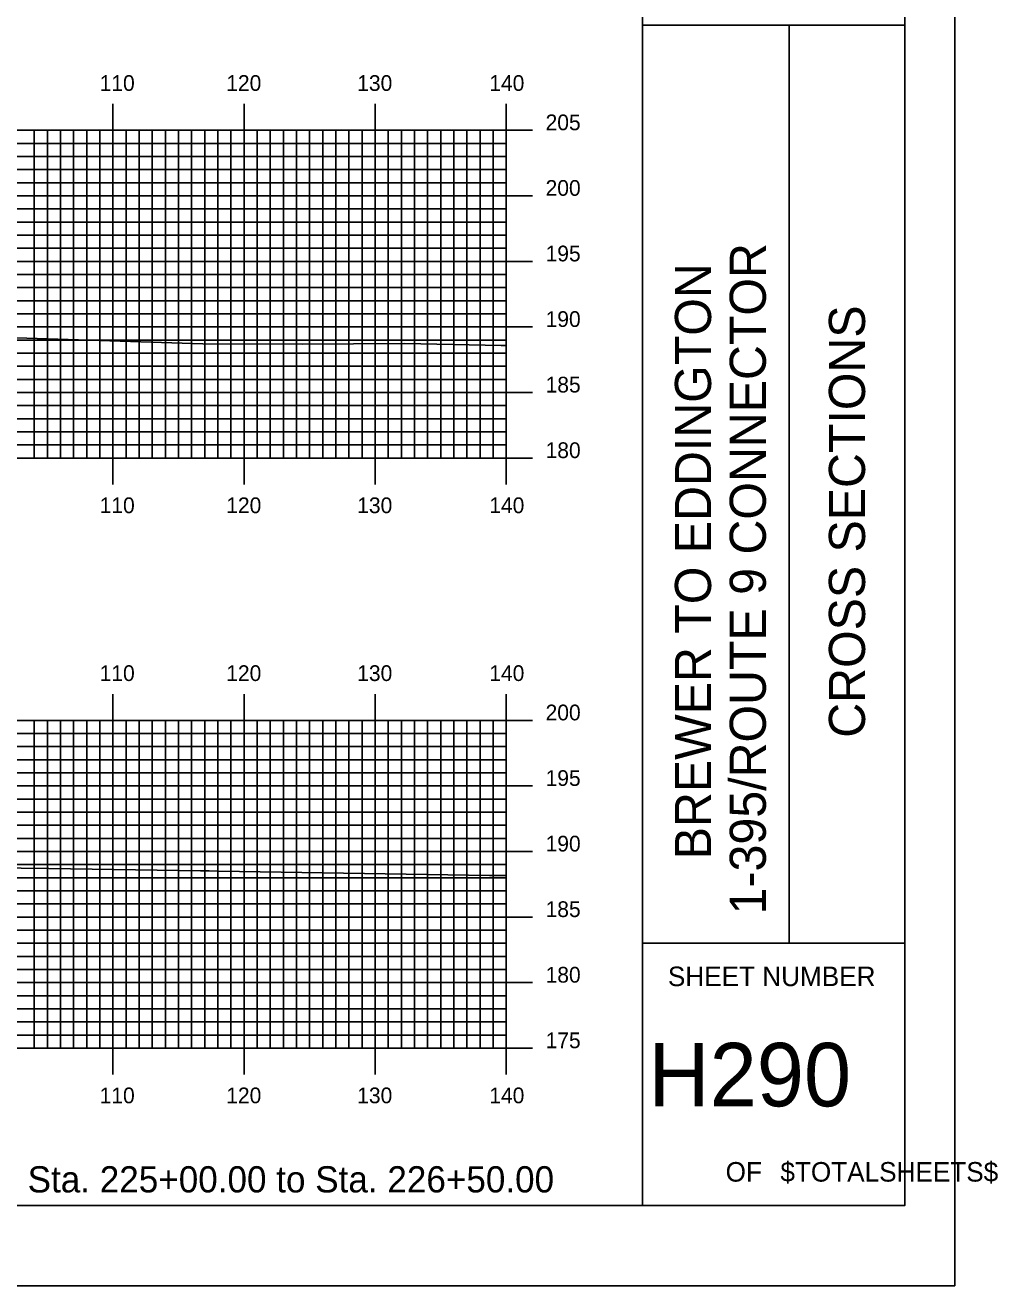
# Model space of a CAD drawing. Extents: x 1798388 to 1798731, y 442591 to 442811.
# Drawn here: x 1798656.8 to 1798731, y 442590.5 to 442686.7 of the extents above; entities that cross this region are included whole.
import ezdxf

# ---------------------------------------------------------------- set-up
doc = ezdxf.new("R2010")
doc.units = 0
for name, color, linetype in [('BORDER', 7, 'Continuous'), ('H_V ANNOTATION', 7, 'Continuous'), ('MAJOR', 7, 'Continuous'), ('MINOR', 7, 'Continuous'), ('PLOT BOUNDARY', 7, 'Continuous'), ('S_Roadway_Centerline', 7, 'Continuous')]:
    doc.layers.add(name, color=color, linetype=linetype)

msp = doc.modelspace()

# ---------------------------------------------------------------- linework, layer by layer
at = {"layer": 'BORDER'}
for p, q in [((1798703.871, 442596.665), (1798703.871, 442806.665)), ((1798703.871, 442686.671), (1798723.871, 442686.671)), ((1798715.053, 442616.671), (1798715.053, 442686.671)), ((1798703.871, 442616.671), (1798723.871, 442616.671))]:
    msp.add_line(p, q, dxfattribs=at)
msp.add_lwpolyline([(1798403.871, 442596.665), (1798723.871, 442596.665), (1798723.871, 442806.665), (1798403.871, 442806.665)], close=True, dxfattribs=at)
at = {"layer": 'MAJOR'}
for p, q in [((1798663.471, 442680.669), (1798663.471, 442678.665)), ((1798673.471, 442680.669), (1798673.471, 442678.665)), ((1798683.471, 442680.669), (1798683.471, 442678.665)), ((1798693.471, 442680.669), (1798693.471, 442678.665)), ((1798413.471, 442678.665), (1798693.471, 442678.665)), ((1798413.471, 442678.665), (1798693.471, 442678.665)), ((1798663.471, 442653.665), (1798663.471, 442678.665)), ((1798673.471, 442653.665), (1798673.471, 442678.665)), ((1798683.471, 442653.665), (1798683.471, 442678.665)), ((1798695.475, 442678.665), (1798691.467, 442678.665)), ((1798693.471, 442653.665), (1798693.471, 442678.665)), ((1798693.471, 442653.665), (1798693.471, 442678.665)), ((1798413.471, 442673.665), (1798693.471, 442673.665)), ((1798695.475, 442673.665), (1798691.467, 442673.665)), ((1798413.471, 442668.665), (1798693.471, 442668.665)), ((1798695.475, 442668.665), (1798691.467, 442668.665)), ((1798413.471, 442663.665), (1798693.471, 442663.665)), ((1798695.475, 442663.665), (1798691.467, 442663.665)), ((1798413.471, 442658.665), (1798693.471, 442658.665)), ((1798695.475, 442658.665), (1798691.467, 442658.665)), ((1798413.471, 442653.665), (1798693.471, 442653.665)), ((1798413.471, 442653.665), (1798693.471, 442653.665)), ((1798663.471, 442651.661), (1798663.471, 442653.665)), ((1798673.471, 442651.661), (1798673.471, 442653.665)), ((1798683.471, 442651.661), (1798683.471, 442653.665)), ((1798695.475, 442653.665), (1798691.467, 442653.665)), ((1798693.471, 442651.661), (1798693.471, 442653.665)), ((1798663.471, 442635.669), (1798663.471, 442633.665)), ((1798673.471, 442635.669), (1798673.471, 442633.665)), ((1798683.471, 442635.669), (1798683.471, 442633.665)), ((1798693.471, 442635.669), (1798693.471, 442633.665)), ((1798413.471, 442633.665), (1798693.471, 442633.665)), ((1798413.471, 442633.665), (1798693.471, 442633.665)), ((1798663.471, 442608.665), (1798663.471, 442633.665)), ((1798673.471, 442608.665), (1798673.471, 442633.665)), ((1798683.471, 442608.665), (1798683.471, 442633.665)), ((1798695.475, 442633.665), (1798691.467, 442633.665)), ((1798693.471, 442608.665), (1798693.471, 442633.665)), ((1798693.471, 442608.665), (1798693.471, 442633.665)), ((1798413.471, 442628.665), (1798693.471, 442628.665)), ((1798695.475, 442628.665), (1798691.467, 442628.665)), ((1798413.471, 442623.665), (1798693.471, 442623.665)), ((1798695.475, 442623.665), (1798691.467, 442623.665)), ((1798413.471, 442618.665), (1798693.471, 442618.665)), ((1798695.475, 442618.665), (1798691.467, 442618.665)), ((1798413.471, 442613.665), (1798693.471, 442613.665)), ((1798695.475, 442613.665), (1798691.467, 442613.665)), ((1798413.471, 442608.665), (1798693.471, 442608.665)), ((1798413.471, 442608.665), (1798693.471, 442608.665)), ((1798663.471, 442606.661), (1798663.471, 442608.665)), ((1798673.471, 442606.661), (1798673.471, 442608.665)), ((1798683.471, 442606.661), (1798683.471, 442608.665)), ((1798695.475, 442608.665), (1798691.467, 442608.665)), ((1798693.471, 442606.661), (1798693.471, 442608.665))]:
    msp.add_line(p, q, dxfattribs=at)
at = {"layer": 'MINOR'}
for p, q in [((1798657.471, 442653.665), (1798657.471, 442678.665)), ((1798658.471, 442653.665), (1798658.471, 442678.665)), ((1798659.471, 442653.665), (1798659.471, 442678.665)), ((1798660.471, 442653.665), (1798660.471, 442678.665)), ((1798661.471, 442653.665), (1798661.471, 442678.665)), ((1798662.471, 442653.665), (1798662.471, 442678.665)), ((1798664.471, 442653.665), (1798664.471, 442678.665)), ((1798665.471, 442653.665), (1798665.471, 442678.665)), ((1798666.471, 442653.665), (1798666.471, 442678.665)), ((1798667.471, 442653.665), (1798667.471, 442678.665)), ((1798668.471, 442653.665), (1798668.471, 442678.665)), ((1798669.471, 442653.665), (1798669.471, 442678.665)), ((1798670.471, 442653.665), (1798670.471, 442678.665)), ((1798671.471, 442653.665), (1798671.471, 442678.665)), ((1798672.471, 442653.665), (1798672.471, 442678.665)), ((1798674.471, 442653.665), (1798674.471, 442678.665)), ((1798675.471, 442653.665), (1798675.471, 442678.665)), ((1798676.471, 442653.665), (1798676.471, 442678.665)), ((1798677.471, 442653.665), (1798677.471, 442678.665)), ((1798678.471, 442653.665), (1798678.471, 442678.665)), ((1798679.471, 442653.665), (1798679.471, 442678.665)), ((1798680.471, 442653.665), (1798680.471, 442678.665)), ((1798681.471, 442653.665), (1798681.471, 442678.665)), ((1798682.471, 442653.665), (1798682.471, 442678.665)), ((1798684.471, 442653.665), (1798684.471, 442678.665)), ((1798685.471, 442653.665), (1798685.471, 442678.665)), ((1798686.471, 442653.665), (1798686.471, 442678.665)), ((1798687.471, 442653.665), (1798687.471, 442678.665)), ((1798688.471, 442653.665), (1798688.471, 442678.665)), ((1798689.471, 442653.665), (1798689.471, 442678.665)), ((1798690.471, 442653.665), (1798690.471, 442678.665)), ((1798691.471, 442653.665), (1798691.471, 442678.665)), ((1798692.471, 442653.665), (1798692.471, 442678.665)), ((1798413.471, 442677.665), (1798693.471, 442677.665)), ((1798693.471, 442677.665), (1798691.467, 442677.665)), ((1798413.471, 442676.665), (1798693.471, 442676.665)), ((1798693.471, 442676.665), (1798691.467, 442676.665)), ((1798413.471, 442675.665), (1798693.471, 442675.665)), ((1798693.471, 442675.665), (1798691.467, 442675.665)), ((1798413.471, 442674.665), (1798693.471, 442674.665)), ((1798693.471, 442674.665), (1798691.467, 442674.665)), ((1798413.471, 442672.665), (1798693.471, 442672.665)), ((1798693.471, 442672.665), (1798691.467, 442672.665)), ((1798413.471, 442671.665), (1798693.471, 442671.665)), ((1798693.471, 442671.665), (1798691.467, 442671.665)), ((1798413.471, 442670.665), (1798693.471, 442670.665)), ((1798693.471, 442670.665), (1798691.467, 442670.665)), ((1798413.471, 442669.665), (1798693.471, 442669.665)), ((1798693.471, 442669.665), (1798691.467, 442669.665)), ((1798413.471, 442667.665), (1798693.471, 442667.665)), ((1798693.471, 442667.665), (1798691.467, 442667.665)), ((1798413.471, 442666.665), (1798693.471, 442666.665)), ((1798693.471, 442666.665), (1798691.467, 442666.665)), ((1798413.471, 442665.665), (1798693.471, 442665.665)), ((1798693.471, 442665.665), (1798691.467, 442665.665)), ((1798413.471, 442664.665), (1798693.471, 442664.665)), ((1798693.471, 442664.665), (1798691.467, 442664.665)), ((1798413.471, 442662.665), (1798693.471, 442662.665)), ((1798693.471, 442662.665), (1798691.467, 442662.665)), ((1798413.471, 442661.665), (1798693.471, 442661.665)), ((1798693.471, 442661.665), (1798691.467, 442661.665)), ((1798413.471, 442660.665), (1798693.471, 442660.665)), ((1798693.471, 442660.665), (1798691.467, 442660.665)), ((1798413.471, 442659.665), (1798693.471, 442659.665)), ((1798693.471, 442659.665), (1798691.467, 442659.665)), ((1798413.471, 442657.665), (1798693.471, 442657.665)), ((1798693.471, 442657.665), (1798691.467, 442657.665)), ((1798413.471, 442656.665), (1798693.471, 442656.665)), ((1798693.471, 442656.665), (1798691.467, 442656.665)), ((1798413.471, 442655.665), (1798693.471, 442655.665)), ((1798693.471, 442655.665), (1798691.467, 442655.665)), ((1798413.471, 442654.665), (1798693.471, 442654.665)), ((1798693.471, 442654.665), (1798691.467, 442654.665)), ((1798657.471, 442608.665), (1798657.471, 442633.665)), ((1798658.471, 442608.665), (1798658.471, 442633.665)), ((1798659.471, 442608.665), (1798659.471, 442633.665)), ((1798660.471, 442608.665), (1798660.471, 442633.665)), ((1798661.471, 442608.665), (1798661.471, 442633.665)), ((1798662.471, 442608.665), (1798662.471, 442633.665)), ((1798664.471, 442608.665), (1798664.471, 442633.665)), ((1798665.471, 442608.665), (1798665.471, 442633.665)), ((1798666.471, 442608.665), (1798666.471, 442633.665)), ((1798667.471, 442608.665), (1798667.471, 442633.665)), ((1798668.471, 442608.665), (1798668.471, 442633.665)), ((1798669.471, 442608.665), (1798669.471, 442633.665)), ((1798670.471, 442608.665), (1798670.471, 442633.665)), ((1798671.471, 442608.665), (1798671.471, 442633.665)), ((1798672.471, 442608.665), (1798672.471, 442633.665)), ((1798674.471, 442608.665), (1798674.471, 442633.665)), ((1798675.471, 442608.665), (1798675.471, 442633.665)), ((1798676.471, 442608.665), (1798676.471, 442633.665)), ((1798677.471, 442608.665), (1798677.471, 442633.665)), ((1798678.471, 442608.665), (1798678.471, 442633.665)), ((1798679.471, 442608.665), (1798679.471, 442633.665)), ((1798680.471, 442608.665), (1798680.471, 442633.665)), ((1798681.471, 442608.665), (1798681.471, 442633.665)), ((1798682.471, 442608.665), (1798682.471, 442633.665)), ((1798684.471, 442608.665), (1798684.471, 442633.665)), ((1798685.471, 442608.665), (1798685.471, 442633.665)), ((1798686.471, 442608.665), (1798686.471, 442633.665)), ((1798687.471, 442608.665), (1798687.471, 442633.665)), ((1798688.471, 442608.665), (1798688.471, 442633.665)), ((1798689.471, 442608.665), (1798689.471, 442633.665)), ((1798690.471, 442608.665), (1798690.471, 442633.665)), ((1798691.471, 442608.665), (1798691.471, 442633.665)), ((1798692.471, 442608.665), (1798692.471, 442633.665)), ((1798413.471, 442632.665), (1798693.471, 442632.665)), ((1798693.471, 442632.665), (1798691.467, 442632.665)), ((1798413.471, 442631.665), (1798693.471, 442631.665)), ((1798693.471, 442631.665), (1798691.467, 442631.665)), ((1798413.471, 442630.665), (1798693.471, 442630.665)), ((1798693.471, 442630.665), (1798691.467, 442630.665)), ((1798413.471, 442629.665), (1798693.471, 442629.665)), ((1798693.471, 442629.665), (1798691.467, 442629.665)), ((1798413.471, 442627.665), (1798693.471, 442627.665)), ((1798693.471, 442627.665), (1798691.467, 442627.665)), ((1798413.471, 442626.665), (1798693.471, 442626.665)), ((1798693.471, 442626.665), (1798691.467, 442626.665)), ((1798413.471, 442625.665), (1798693.471, 442625.665)), ((1798693.471, 442625.665), (1798691.467, 442625.665)), ((1798413.471, 442624.665), (1798693.471, 442624.665)), ((1798693.471, 442624.665), (1798691.467, 442624.665)), ((1798413.471, 442622.665), (1798693.471, 442622.665)), ((1798693.471, 442622.665), (1798691.467, 442622.665)), ((1798413.471, 442621.665), (1798693.471, 442621.665)), ((1798693.471, 442621.665), (1798691.467, 442621.665)), ((1798413.471, 442620.665), (1798693.471, 442620.665)), ((1798693.471, 442620.665), (1798691.467, 442620.665)), ((1798413.471, 442619.665), (1798693.471, 442619.665)), ((1798693.471, 442619.665), (1798691.467, 442619.665)), ((1798413.471, 442617.665), (1798693.471, 442617.665)), ((1798693.471, 442617.665), (1798691.467, 442617.665)), ((1798413.471, 442616.665), (1798693.471, 442616.665)), ((1798693.471, 442616.665), (1798691.467, 442616.665)), ((1798413.471, 442615.665), (1798693.471, 442615.665)), ((1798693.471, 442615.665), (1798691.467, 442615.665)), ((1798413.471, 442614.665), (1798693.471, 442614.665)), ((1798693.471, 442614.665), (1798691.467, 442614.665)), ((1798413.471, 442612.665), (1798693.471, 442612.665)), ((1798693.471, 442612.665), (1798691.467, 442612.665)), ((1798413.471, 442611.665), (1798693.471, 442611.665)), ((1798693.471, 442611.665), (1798691.467, 442611.665)), ((1798413.471, 442610.665), (1798693.471, 442610.665)), ((1798693.471, 442610.665), (1798691.467, 442610.665)), ((1798413.471, 442609.665), (1798693.471, 442609.665)), ((1798693.471, 442609.665), (1798691.467, 442609.665))]:
    msp.add_line(p, q, dxfattribs=at)
at = {"layer": 'PLOT BOUNDARY'}
msp.add_lwpolyline([(1798387.684, 442590.547), (1798727.684, 442590.547), (1798727.684, 442810.547), (1798387.684, 442810.547)], close=True, dxfattribs=at)
at = {"layer": 'S_Roadway_Centerline'}
for points in [[(1798584.086, 442664.224), (1798602.093, 442663.271), (1798606.309, 442663.191), (1798615.813, 442663.21), (1798627.556, 442663.081), (1798639.409, 442662.81), (1798649.898, 442662.961), (1798651.851, 442663.051), (1798653.725, 442662.909), (1798670.339, 442662.376), (1798677.906, 442662.346), (1798685.723, 442662.392), (1798693.093, 442662.252), (1798693.471, 442662.253)], [(1798596.584, 442622.756), (1798602.182, 442622.746), (1798606.4, 442622.808), (1798619.782, 442622.632), (1798626.635, 442622.485), (1798635.708, 442622.868), (1798647, 442622.514), (1798647.562, 442622.498), (1798647.996, 442622.497), (1798658.581, 442622.367), (1798670.157, 442622.188), (1798670.819, 442622.187), (1798671.532, 442622.163), (1798692.206, 442621.837), (1798693.471, 442621.826)]]:
    msp.add_lwpolyline(points, dxfattribs=at)

# ---------------------------------------------------------------- texts
at = {"layer": 'BORDER'}
for s, p in [('1-395/ROUTE 9 CONNECTOR', (1798713.274, 442618.865)), ('BREWER TO EDDINGTON', (1798709.094, 442623.074)), ('CROSS SECTIONS', (1798720.84, 442632.339))]:
    msp.add_text(s, height=2.75575, rotation=90, dxfattribs=at).set_placement(p)
for s, height, p in [('SHEET NUMBER', 1.49054, (1798705.802, 442613.398)), ('H290', 4.8388, (1798704.31, 442604.23)), ('OF', 1.4905, (1798710.205, 442598.491)), ('$TOTALSHEETS$', 1.49054, (1798714.384, 442598.491))]:
    msp.add_text(s, height=height, dxfattribs=at).set_placement(p)
at = {"layer": 'H_V ANNOTATION'}
for s, height, p in [('110', 1.2, (1798662.454, 442681.665)), ('120', 1.2, (1798672.111, 442681.665)), ('130', 1.2, (1798682.101, 442681.665)), ('140', 1.2, (1798692.176, 442681.665)), ('205', 1.2, (1798696.471, 442678.665)), ('200', 1.2, (1798696.471, 442673.665)), ('195', 1.2, (1798696.471, 442668.665)), ('190', 1.2, (1798696.471, 442663.665)), ('185', 1.2, (1798696.471, 442658.665)), ('180', 1.2, (1798696.471, 442653.665)), ('110', 1.2, (1798662.454, 442649.465)), ('120', 1.2, (1798672.111, 442649.465)), ('130', 1.2, (1798682.101, 442649.465)), ('140', 1.2, (1798692.176, 442649.465)), ('110', 1.2, (1798662.454, 442636.665)), ('120', 1.2, (1798672.111, 442636.665)), ('130', 1.2, (1798682.101, 442636.665)), ('140', 1.2, (1798692.176, 442636.665)), ('200', 1.2, (1798696.471, 442633.665)), ('195', 1.2, (1798696.471, 442628.665)), ('190', 1.2, (1798696.471, 442623.665)), ('185', 1.2, (1798696.471, 442618.665)), ('180', 1.2, (1798696.471, 442613.665)), ('175', 1.2, (1798696.471, 442608.665)), ('110', 1.2, (1798662.454, 442604.465)), ('120', 1.2, (1798672.111, 442604.465)), ('130', 1.2, (1798682.101, 442604.465)), ('140', 1.2, (1798692.176, 442604.465)), ('Sta. 225+00.00 to Sta. 226+50.00', 2.0004, (1798656.962, 442597.665))]:
    msp.add_text(s, height=height, dxfattribs=at).set_placement(p)

doc.saveas('drawing.dxf')
